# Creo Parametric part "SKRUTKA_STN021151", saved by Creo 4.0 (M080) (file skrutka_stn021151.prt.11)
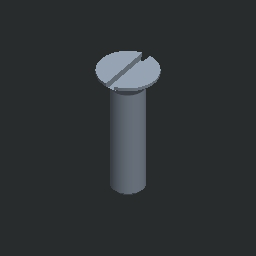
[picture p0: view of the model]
Units: Custom; MM, KILOGRAM, SECS
Materials in the file: OCEL, OCEL_N

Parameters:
  PTC_MATERIAL_NAME = "OCEL"
  NAZOV = "SKRUTKA_STN021151"
  NORMA = "STN 02 1151"

Other parameters: HMOTNOST, HUSTOTA

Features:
  1. datum plane "DTM1"
  2. cut
  3. round
  4. chamfer
  5. datum plane "DTM2"
  6. datum plane "DTM3"

Other named items: BLIND

Layers: 1, 2, 3, 4, 5, 6, 7, 8, 9, 10, 11, 12, 13, 14, 15, 16, 17, 18, 19, 20, 21, 22, 23, 24, 25, 26, 27, 28, 29, 30, 31, 32

Family table entries: GENERIC, SKRUTKA_M1, SKRUTKA_STN021151, value(d_val), value(i_val), SKRUTKA_M1_2, SKRUTKA_STN021151, SKRUTKA_M1_6, SKRUTKA_STN021151, SKRUTKA_M2, SKRUTKA_STN021151, SKRUTKA_M2_5, SKRUTKA_STN021151, SKRUTKA_M3, SKRUTKA_STN021151, SKRUTKA_M3_5, SKRUTKA_STN021151, SKRUTKA_M4, SKRUTKA_STN021151, SKRUTKA_M5, SKRUTKA_STN021151, SKRUTKA_M6, SKRUTKA_STN021151, 2/&, SKRUTKA_M8, SKRUTKA_STN021151, !/ , 2/., SKRUTKA_M10, SKRUTKA_STN021151, !/$, 2/2, SKRUTKA_M12, SKRUTKA_STN021151, !/(, SKRUTKA_M16, SKRUTKA_STN021151, !/0, 2/;, SKRUTKA_M20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

Surfaces: 8 plane, 5 cylinder, 4 cone, 2 torus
